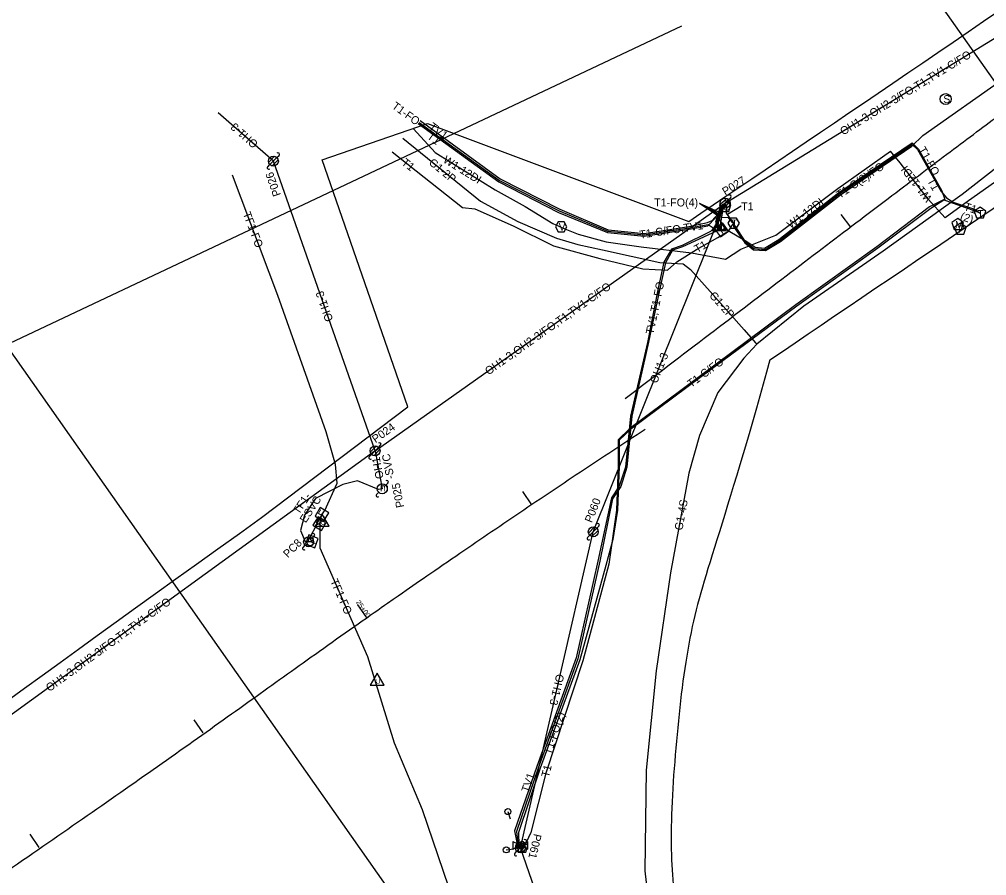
# Model space of a CAD drawing. Extents: x 1991878 to 2008544, y 770238 to 1141211.
# Drawn here: x 2004972.5 to 2005456, y 1139564 to 1139992.3 of the extents above; entities that cross this region are included whole.
import ezdxf

# ---------------------------------------------------------------- set-up
doc = ezdxf.new("R2010")
doc.units = 0
for name, color, linetype in [('RD_EX_SU_Elec', 7, 'Continuous'), ('RD_EX_SU_Gas', 7, 'Continuous'), ('RD_EX_SU_H2O', 7, 'Continuous'), ('RD_EX_SU_Misc', 7, 'Continuous'), ('RD_EX_SU_Ovhd', 7, 'Continuous'), ('RD_EX_SU_Pole', 7, 'Continuous'), ('RD_EX_SU_Sewer', 7, 'Continuous'), ('RD_EX_SU_SwpLmt', 7, 'Continuous'), ('RD_EX_SU_Telecom', 7, 'Continuous'), ('RD_EX_SU_Trfc', 7, 'Continuous'), ('RD_EX_SU_TX_Gas', 7, 'Continuous'), ('RD_EX_SU_TX_H2O', 7, 'Continuous'), ('RD_EX_SU_TX_Ovhd', 7, 'Continuous'), ('RD_EX_SU_TX_Pole', 7, 'Continuous'), ('RD_EX_SU_TX_Telecom', 7, 'Continuous'), ('RD_EX_SU_TX_Trfc', 7, 'Continuous'), ('RD_HC_Cl', 7, 'Continuous')]:
    doc.layers.add(name, color=color, linetype=linetype)

# ---------------------------------------------------------------- blocks, each defined once
blk = doc.blocks.new('GW')
at = {"layer": 'RD_EX_SU_Pole'}
blk.add_line((0, 0), (0, 5), dxfattribs=at)
blk.add_circle((0, 0), 2, dxfattribs=at)

msp = doc.modelspace()

# ---------------------------------------------------------------- linework, layer by layer
at = {"layer": 'RD_EX_SU_Elec'}
msp.add_lwpolyline([(2005153.85, 1139757.47), (2005152.02, 1139757.14), (2005141.45, 1139761.42), (2005134.15, 1139759.67), (2005120.43, 1139752.58), (2005114.98, 1139744.32), (2005113, 1139736.52), (2005115.35, 1139731.05), (2005117.06, 1139730.96)], dxfattribs=at)
at = {"layer": 'RD_EX_SU_Gas'}
for points in [[(2005803.2, 1140176.39), (2005763.13, 1140146.95), (2005723.81, 1140118.19), (2005683.92, 1140086.83), (2005644.62, 1140056.74), (2005604.18, 1140027.33), (2005564.31, 1139998.64), (2005521.91, 1139966.72), (2005504.56, 1139952.57), (2005484.04, 1139936.17), (2005443.65, 1139904.67), (2005433.24, 1139897.21), (2005404.27, 1139876.33), (2005364.62, 1139848.8), (2005341.03, 1139829.73), (2005334.6, 1139822.82), (2005321.62, 1139805.66), (2005312.49, 1139784.03), (2005307.05, 1139765.3), (2005297.89, 1139715.34), (2005290.82, 1139666.35), (2005285.78, 1139616.8), (2005285.17, 1139566.36), (2005290.52, 1139518.04)], [(2005164.18, 1139932.85), (2005202.91, 1139901.24), (2005221.58, 1139891.11), (2005240.96, 1139882.82), (2005251.57, 1139879.59), (2005264.01, 1139876.97), (2005292.58, 1139870.62), (2005304.26, 1139870.04), (2005307.88, 1139867.17), (2005317.77, 1139856.07), (2005334.76, 1139836.96), (2005340.45, 1139830.49), (2005341.03, 1139829.73)]]:
    msp.add_lwpolyline(points, dxfattribs=at)
at = {"layer": 'RD_EX_SU_H2O'}
for points in [[(2005807.57, 1140171.15), (2005766.02, 1140142.13), (2005735.93, 1140120.52), (2005732.28, 1140118.09), (2005726.84, 1140114.53), (2005714.88, 1140105.91), (2005686.65, 1140083.86), (2005647.25, 1140052.78), (2005607.69, 1140020.33), (2005569.36, 1139991.81), (2005526.81, 1139959.7), (2005492.34, 1139933.84), (2005487.01, 1139929.87), (2005446.84, 1139901.54), (2005435.17, 1139892.92), (2005426.67, 1139902.32), (2005412.65, 1139920.51), (2005407.97, 1139926.34)], [(2005169.51, 1139937.42), (2005180.22, 1139925.59), (2005210.25, 1139906.98), (2005225.26, 1139898.61), (2005239.13, 1139890.18), (2005245.16, 1139887.44), (2005251.72, 1139884.74), (2005265.7, 1139881), (2005283.32, 1139878.42), (2005308.46, 1139875.51), (2005325.36, 1139872.3), (2005333.15, 1139877.37), (2005350.62, 1139884.25), (2005381.59, 1139907.64), (2005407.97, 1139926.34)]]:
    msp.add_lwpolyline(points, dxfattribs=at)
for points in [[(2005246.17, 1139888.44), (2005244.72, 1139890.94), (2005241.84, 1139890.94), (2005240.39, 1139888.44), (2005241.84, 1139885.94), (2005244.72, 1139885.94)], [(2005441.53, 1139892.71), (2005438.62, 1139890.6), (2005439.73, 1139887.19), (2005443.32, 1139887.19), (2005444.43, 1139890.6)], [(2005442.82, 1139890.37), (2005439.92, 1139888.27), (2005441.03, 1139884.86), (2005444.61, 1139884.86), (2005445.72, 1139888.27)]]:
    msp.add_lwpolyline(points, close=True, dxfattribs=at)
at = {"layer": 'RD_EX_SU_Misc'}
for points in [[(2005322.31, 1139892.63), (2005318.84, 1139886.63), (2005325.77, 1139886.63)], [(2005123.83, 1139744.73), (2005120.37, 1139738.73), (2005127.3, 1139738.73)], [(2005151.32, 1139665.16), (2005147.86, 1139659.16), (2005154.79, 1139659.16)]]:
    msp.add_lwpolyline(points, close=True, dxfattribs=at)
at = {"layer": 'RD_EX_SU_Ovhd'}
for p, q in [((2005325.23, 1139900.3), (2005507.86, 1140012.14)), ((2005099.43, 1139921.35), (2005071.87, 1139945.5)), ((2005150.23, 1139776.39), (2005099.43, 1139921.35)), ((2005150.23, 1139776.39), (2005325.23, 1139900.3)), ((2005259.34, 1139735.98), (2005325.23, 1139900.3)), ((2005150.23, 1139776.39), (2004885.7, 1139584.32)), ((2005150.23, 1139776.39), (2005153.85, 1139757.47)), ((2005222.89, 1139577.92), (2005259.34, 1139735.98)), ((2005312.61, 1139322.78), (2005222.89, 1139577.92))]:
    msp.add_line(p, q, dxfattribs=at)
at = {"layer": 'RD_EX_SU_Pole'}
for p, q in [((2005097.01, 1139920.7), (2005100.07, 1139923.76)), ((2005097.66, 1139919.58), (2005101.19, 1139923.12)), ((2005098.78, 1139918.93), (2005101.84, 1139922)), ((2005101.19, 1139923.12), (2005102.25, 1139924.18)), ((2005096.6, 1139918.52), (2005097.66, 1139919.58)), ((2005322.81, 1139899.65), (2005325.88, 1139902.71)), ((2005323.46, 1139898.53), (2005327, 1139902.07)), ((2005324.58, 1139897.88), (2005327.64, 1139900.94)), ((2005327, 1139902.07), (2005328.06, 1139903.13)), ((2005322.4, 1139897.47), (2005323.46, 1139898.53)), ((2005147.81, 1139775.74), (2005150.87, 1139778.8)), ((2005148.46, 1139774.62), (2005151.99, 1139778.16)), ((2005149.58, 1139773.98), (2005152.64, 1139777.04)), ((2005151.99, 1139778.16), (2005153.05, 1139779.22)), ((2005147.4, 1139773.56), (2005148.46, 1139774.62)), ((2005155.62, 1139759.24), (2005156.68, 1139760.3)), ((2005151.02, 1139754.65), (2005152.08, 1139755.71)), ((2005256.92, 1139735.33), (2005259.98, 1139738.4)), ((2005257.57, 1139734.21), (2005261.1, 1139737.75)), ((2005258.69, 1139733.57), (2005261.75, 1139736.63)), ((2005261.1, 1139737.75), (2005262.16, 1139738.81)), ((2005256.51, 1139733.15), (2005257.57, 1139734.21)), ((2005220.48, 1139577.27), (2005223.54, 1139580.33)), ((2005221.13, 1139576.15), (2005224.66, 1139579.68)), ((2005222.25, 1139575.5), (2005225.31, 1139578.56)), ((2005224.66, 1139579.68), (2005225.72, 1139580.74)), ((2005220.07, 1139575.09), (2005221.13, 1139576.15))]:
    msp.add_line(p, q, dxfattribs=at)
for centre in [(2005099.43, 1139921.35), (2005325.23, 1139900.3), (2005150.23, 1139776.39), (2005153.85, 1139757.47), (2005259.34, 1139735.98), (2005222.89, 1139577.92)]:
    msp.add_circle(centre, 2.5, dxfattribs=at)
for centre, start, end in [((2005101.72, 1139924.71), 315.0116, 135.0116), ((2005097.13, 1139917.99), 135.0116, 315.0116), ((2005327.53, 1139903.66), 315.0116, 135.0116), ((2005322.93, 1139896.94), 135.0116, 315.0116), ((2005152.52, 1139779.75), 315.0116, 135.0116), ((2005147.93, 1139773.03), 135.0116, 315.0116), ((2005156.15, 1139760.83), 315.0116, 135.0116), ((2005151.55, 1139754.11), 135.0116, 315.0116), ((2005261.63, 1139739.34), 315.0116, 135.0116), ((2005257.04, 1139732.62), 135.0116, 315.0116), ((2005225.19, 1139581.28), 315.0116, 135.0116), ((2005220.6, 1139574.56), 135.0116, 315.0116)]:
    msp.add_arc(centre, 0.75, start, end, dxfattribs=at)
at = {"layer": 'RD_EX_SU_Sewer'}
msp.add_circle((2005435.49, 1139952.36), 2.75, dxfattribs=at)
at = {"layer": 'RD_EX_SU_SwpLmt'}
for p, q in [((2005123.81, 1139921.92), (2005176.42, 1139940.17)), ((2005176.42, 1139940.17), (2005307.04, 1139891.13)), ((2005166.65, 1139798.43), (2005123.81, 1139921.92)), ((2005093.47, 1139743.03), (2005166.65, 1139798.43))]:
    msp.add_line(p, q, dxfattribs=at)
for points in [[(2005347.6, 1139821.95), (2005413.49, 1139866.73), (2005588.16, 1139984.08), (2005817.83, 1140151.69), (2006031.43, 1140278.81), (2006110.28, 1140318.03), (2006387.29, 1140416.7), (2006495.91, 1140463.06), (2006601.39, 1140518.44), (2006718.46, 1140585.62), (2006783.57, 1140627.26), (2006823.57, 1140659.06)], [(2005347.6, 1139821.95), (2005413.49, 1139866.73), (2005588.16, 1139984.08), (2005817.83, 1140151.69), (2006031.43, 1140278.81), (2006110.28, 1140318.03), (2006387.29, 1140416.7), (2006495.91, 1140463.06), (2006601.39, 1140518.44), (2006706.19, 1140578.58), (2006762.55, 1140613.92), (2006787.85, 1140632.08)], [(2005307.04, 1139891.13), (2005371.11, 1139934.66), (2005544.09, 1140050.96), (2005773.7, 1140218.52), (2005993.11, 1140349.1), (2006068.08, 1140386.39), (2006199.13, 1140434.31), (2006247.03, 1140451.84)], [(2005347.6, 1139821.95), (2005338.82, 1139789.17), (2005319.63, 1139726.83), (2005307.21, 1139688.02), (2005300.75, 1139635.07), (2005296.98, 1139579.17), (2005300.89, 1139544.34), (2005306.71, 1139501.41), (2005336.4, 1139410.85), (2005354.58, 1139357.93), (2005354.93, 1139356.91), (2005370.8, 1139309.82)], [(2004667.64, 1139426.86), (2004691.38, 1139445.04), (2004818.69, 1139542.26), (2004974.3, 1139658.1), (2005093.47, 1139743.03)]]:
    msp.add_open_spline(points, degree=3, dxfattribs=at)
at = {"layer": 'RD_EX_SU_Telecom'}
for p, q in [((2005325.27, 1139898.61), (2005325.23, 1139900.3)), ((2005219.19, 1139581.04), (2005221.59, 1139579.84)), ((2005219.19, 1139581.04), (2005219.19, 1139577.29)), ((2005219.19, 1139577.29), (2005221.59, 1139578.5)), ((2005224.28, 1139579.84), (2005226.69, 1139581.04)), ((2005224.28, 1139578.5), (2005226.69, 1139577.29)), ((2005226.69, 1139577.29), (2005226.69, 1139581.04))]:
    msp.add_line(p, q, dxfattribs=at)
for points in [[(2005329.54, 1139890.24), (2005329.5, 1139888.67), (2005335.08, 1139880.48), (2005339.37, 1139876.95), (2005345.48, 1139876.61), (2005352.84, 1139881.19), (2005382.96, 1139904.56), (2005418.59, 1139928.8), (2005424.14, 1139934.13), (2005465.15, 1139963.24), (2005505.66, 1139991.65), (2005514.4, 1139998.22), (2005511.6, 1140003.28), (2005507.15, 1140008.6), (2005506.12, 1140009.88)], [(2005171.75, 1139940.12), (2005212.08, 1139911), (2005241.92, 1139895.72), (2005266.39, 1139885.63), (2005284.76, 1139883.81), (2005307.34, 1139887.23), (2005316.54, 1139888.98), (2005320.48, 1139892.91), (2005326.52, 1139893.28), (2005328.52, 1139890.85), (2005329.54, 1139890.24)], [(2005172.34, 1139940.64), (2005212.43, 1139911.58), (2005242.31, 1139896.48), (2005266.6, 1139886.33), (2005284.77, 1139884.5), (2005307.19, 1139887.91), (2005316.75, 1139889.61), (2005320.71, 1139887.02), (2005323.48, 1139886.9)], [(2005172.72, 1139941.65), (2005212.71, 1139912.43), (2005242.55, 1139897.35), (2005266.74, 1139886.95), (2005284.79, 1139885.19), (2005307.04, 1139888.71), (2005316.48, 1139890.57), (2005318.72, 1139891.61), (2005324.67, 1139898.08), (2005325.27, 1139898.61)], [(2005323.48, 1139886.9), (2005325.65, 1139887.26), (2005336.03, 1139881.17), (2005340.25, 1139878.22), (2005344.85, 1139877.72), (2005352.12, 1139882.19), (2005382.15, 1139905.62), (2005418.71, 1139930.43), (2005421.88, 1139927.35), (2005433.64, 1139906.53), (2005435.1, 1139902.1), (2005428.12, 1139897.63), (2005401.53, 1139877.88), (2005361, 1139848.83), (2005313.26, 1139813.53), (2005278.11, 1139787.32), (2005272.33, 1139781.85), (2005272.33, 1139768.79), (2005271.52, 1139746.7), (2005269.11, 1139732.16), (2005265.54, 1139719.16), (2005252.68, 1139671.84), (2005232.78, 1139617.8), (2005222.03, 1139585.56), (2005222.06, 1139579.11), (2005222.89, 1139577.92)], [(2005329.54, 1139890.24), (2005329.86, 1139889.11), (2005335.43, 1139880.78), (2005339.78, 1139877.62), (2005345.17, 1139877.11), (2005352.59, 1139881.68), (2005382.53, 1139905.07), (2005418.67, 1139929.59), (2005421.43, 1139927.09), (2005433.28, 1139906.21), (2005435.94, 1139902.99), (2005439.28, 1139900.88), (2005449.89, 1139897.26), (2005452.64, 1139895.36)], [(2005158.82, 1139925.96), (2005194.01, 1139898.12), (2005200.13, 1139897.55), (2005219.33, 1139888.94), (2005239.37, 1139879.01), (2005262.65, 1139872.69), (2005284.07, 1139867.44), (2005296.49, 1139866.87), (2005301.04, 1139871.01), (2005310.97, 1139877.21), (2005321.57, 1139883.12), (2005327.15, 1139886.4), (2005328.52, 1139889), (2005329.54, 1139890.24)], [(2005452.64, 1139895.36), (2005449.47, 1139896.61), (2005438.94, 1139900.34), (2005434.37, 1139902.01), (2005427.42, 1139898.46), (2005401.04, 1139878.44), (2005360.59, 1139849.53), (2005312.98, 1139813.98), (2005277.67, 1139787.66), (2005271.77, 1139782), (2005271.7, 1139768.83), (2005270.97, 1139746.75), (2005267.19, 1139719.78), (2005254.18, 1139671.36), (2005235.57, 1139615.19), (2005228.17, 1139585.63), (2005224.84, 1139578.41), (2005223.84, 1139578.16), (2005223.71, 1139577.39), (2005222.89, 1139577.92)], [(2005325.27, 1139898.61), (2005324.71, 1139899.01), (2005319.93, 1139888.26), (2005317.91, 1139886.18), (2005303.76, 1139879.2), (2005298.48, 1139877.27), (2005294.63, 1139870.79), (2005291.63, 1139856.89), (2005286.38, 1139830.63), (2005277.9, 1139793.72), (2005275.51, 1139768.28), (2005272.34, 1139758.76), (2005268.4, 1139752.91), (2005261.58, 1139721.28), (2005250.82, 1139672.9), (2005231.12, 1139618.56), (2005220.01, 1139586.46), (2005221.65, 1139577.98), (2005222.89, 1139577.92)], [(2005325.23, 1139900.3), (2005323, 1139898.99), (2005320.44, 1139890.77), (2005321.37, 1139887.39), (2005323.48, 1139886.9)], [(2005325.23, 1139900.3), (2005323.35, 1139898.74), (2005320.98, 1139890.71), (2005321.94, 1139887.71), (2005323.48, 1139886.9)], [(2005325.23, 1139900.3), (2005323.83, 1139898.59), (2005321.82, 1139890.38), (2005322.56, 1139888.17), (2005323.48, 1139886.9)], [(2005325.23, 1139900.3), (2005324.19, 1139898.49), (2005322.85, 1139890.39), (2005323.22, 1139888.38), (2005323.48, 1139886.9)], [(2005329.54, 1139890.24), (2005329.07, 1139891.15), (2005327.21, 1139893.53), (2005325.88, 1139895.39), (2005326.16, 1139899.01), (2005325.45, 1139899.44), (2005325.23, 1139900.3)], [(2005323.48, 1139886.9), (2005320.99, 1139886.27), (2005303.92, 1139878.54), (2005299.01, 1139876.77), (2005295.36, 1139870.46), (2005292.36, 1139856.76), (2005286.91, 1139830.72), (2005278.61, 1139793.76), (2005276.08, 1139768.26), (2005273.03, 1139758.57), (2005268.9, 1139752.48), (2005262.55, 1139721.27), (2005251.64, 1139672.45), (2005231.98, 1139618.24), (2005220.92, 1139586.11), (2005221.87, 1139578.44), (2005222.89, 1139577.92)], [(2005222.94, 1139579.17), (2005223.62, 1139579.04), (2005223.84, 1139578.16)], [(2005223.84, 1139578.16), (2005223.55, 1139578.61), (2005222.94, 1139579.17)]]:
    msp.add_lwpolyline(points, dxfattribs=at)
for points in [[(2005325.27, 1139901.61), (2005322.42, 1139899.54), (2005323.51, 1139896.18), (2005327.03, 1139896.18), (2005328.12, 1139899.54)], [(2005452.64, 1139898.36), (2005449.79, 1139896.29), (2005450.88, 1139892.94), (2005454.41, 1139892.94), (2005455.5, 1139896.29)], [(2005332.43, 1139890.24), (2005330.99, 1139892.74), (2005328.1, 1139892.74), (2005326.66, 1139890.24), (2005328.1, 1139887.74), (2005330.99, 1139887.74)], [(2005324.08, 1139890.39), (2005320, 1139887.5), (2005322.89, 1139883.42), (2005326.97, 1139886.31)], [(2005223.84, 1139581.16), (2005220.99, 1139579.09), (2005222.08, 1139575.73), (2005225.61, 1139575.73), (2005226.7, 1139579.09)]]:
    msp.add_lwpolyline(points, close=True, dxfattribs=at)
msp.add_circle((2005222.94, 1139579.17), 1.5, dxfattribs=at)
at = {"layer": 'RD_EX_SU_Trfc'}
for p, q in [((2005118.83, 1139732.73), (2005119.89, 1139733.79)), ((2005114.24, 1139728.13), (2005115.3, 1139729.19))]:
    msp.add_line(p, q, dxfattribs=at)
for points in [[(2005117.06, 1139730.96), (2005118.67, 1139731.18), (2005117.63, 1139733), (2005121.11, 1139739.66), (2005122.6, 1139740.05), (2005123.69, 1139744.6), (2005125.1, 1139746.6), (2005131.24, 1139760.29), (2005130.4, 1139769.68), (2005125.75, 1139785.91), (2005101.72, 1139854.1), (2005079.02, 1139914.26)], [(2005122.6, 1139740.05), (2005122.66, 1139727.93), (2005146.49, 1139673.59), (2005159.73, 1139630.34), (2005173.87, 1139597.08), (2005202.6, 1139512.33)]]:
    msp.add_lwpolyline(points, dxfattribs=at)
for points in [[(2005122.89, 1139748.04), (2005120.25, 1139743.79), (2005124.49, 1139741.15), (2005127.13, 1139745.4)], [(2005121.8, 1139743.49), (2005119.16, 1139739.25), (2005123.41, 1139736.61), (2005126.05, 1139740.85)], [(2005117.22, 1139734.4), (2005115.45, 1139729.72), (2005120.12, 1139727.95), (2005121.89, 1139732.63)]]:
    msp.add_lwpolyline(points, close=True, dxfattribs=at)
msp.add_circle((2005117.06, 1139730.96), 2.5, dxfattribs=at)
for centre, start, end in [((2005119.36, 1139734.32), 314.9993, 134.9993), ((2005114.77, 1139727.6), 134.9993, 314.9993)]:
    msp.add_arc(centre, 0.75, start, end, dxfattribs=at)
at = {"layer": 'RD_EX_SU_TX_Telecom'}
for p, q in [((2005323.39, 1139893.63), (2005312.48, 1139900.22)), ((2005322.56, 1139893.38), (2005312.48, 1139900.22)), ((2005312.48, 1139900.22), (2005322.23, 1139894.96)), ((2005322.02, 1139895.84), (2005312.48, 1139900.22)), ((2005333.28, 1139898.75), (2005326.42, 1139894.63))]:
    msp.add_line(p, q, dxfattribs=at)
at = {"layer": 'RD_HC_Cl'}
for p, q in [((2005272.89, 1140227.22), (2005691.71, 1139631.08)), ((2005303.45, 1139988.79), (2004595.02, 1139654.18)), ((2004880.13, 1139951.28), (2005298.96, 1139355.14)), ((2005383.05, 1139894.65), (2005387.87, 1139888.26)), ((2005223.99, 1139756.09), (2005228.47, 1139749.46)), ((2005141.5, 1139699.36), (2005146.07, 1139692.8)), ((2005059.59, 1139641.94), (2005064.19, 1139635.4)), ((2004977.69, 1139584.65), (2004982.25, 1139578.08))]:
    msp.add_line(p, q, dxfattribs=at)
for points in [[(2005275.25, 1139802.58), (2005417.33, 1139911.24), (2005548.93, 1140008.55), (2005664.1, 1140090.03), (2005747, 1140153.49), (2005819.82, 1140205.85), (2005880.88, 1140246.35), (2005986.62, 1140308.11), (2006024.68, 1140326.82), (2006100.51, 1140359.48), (2006273.91, 1140424.96), (2006364.15, 1140455.15), (2006461.52, 1140489.97), (2006524.81, 1140519.99), (2006584.45, 1140553.16), (2006699.96, 1140622.09), (2006754.11, 1140664.4), (2006830.67, 1140723.8), (2007317.85, 1141134.95)], [(2002937.27, 1138556.06), (2003081.12, 1138596.24), (2003224.54, 1138636.27), (2003324.8, 1138664.72), (2003440.8, 1138697.76), (2003610.3, 1138743.13), (2003753.45, 1138782.34), (2003851.96, 1138815.09), (2003945.32, 1138855.48), (2004023.07, 1138899.74), (2004117.46, 1138962.96), (2004239.69, 1139051.13), (2004401.3, 1139168.16), (2004522.74, 1139256.47), (2004724.1, 1139402.13), (2005003.72, 1139590.96), (2005189.76, 1139724.82), (2005285.27, 1139787.25)]]:
    msp.add_open_spline(points, degree=2, dxfattribs=at)

# ---------------------------------------------------------------- block references
at = {"layer": 'RD_EX_SU_Pole', "yscale": 0.75}
for p, xscale, rotation in [((2005216.64, 1139596.01), 0.7500000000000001, -160.86037535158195), ((2005215.87, 1139576.85), 0.75, -81.39425926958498)]:
    msp.add_blockref('GW', p, dxfattribs=dict(at, xscale=xscale, rotation=rotation))

# ---------------------------------------------------------------- texts
at = {"layer": 'RD_EX_SU_H2O'}
for s, p in [('M', (2005440.16, 1139887.66)), ('V', (2005242.07, 1139886.56))]:
    msp.add_text(s, height=3.75, dxfattribs=at).set_placement(p)
msp.add_text('P', height=3.75, rotation=360, dxfattribs=at).set_placement((2005441.67, 1139885.45))
at = {"layer": 'RD_EX_SU_Misc'}
for p in [(2005321.55, 1139887.43), (2005123.08, 1139739.53), (2005150.57, 1139659.96)]:
    msp.add_text('U', height=2.4, dxfattribs=at).set_placement(p)
at = {"layer": 'RD_EX_SU_Pole'}
msp.add_text('m', height=4, rotation=0.0116, dxfattribs=at).set_placement((2005152.66, 1139756.15))
at = {"layer": 'RD_EX_SU_Sewer'}
msp.add_text('S', height=3.93, dxfattribs=at).set_placement((2005434.29, 1139950.39))
at = {"layer": 'RD_EX_SU_Telecom'}
for s, height, p in [('C', 4, (2005324.04, 1139896.61)), ('T', 3.75, (2005451.42, 1139893.14)), ('T', 3.75, (2005328.33, 1139888.37)), ('T', 3.75, (2005222.61, 1139575.93))]:
    msp.add_text(s, height=height, dxfattribs=at).set_placement(p)
msp.add_text('F', height=4, rotation=35.2997, dxfattribs=at).set_placement((2005323.71, 1139884.61))
at = {"layer": 'RD_EX_SU_Trfc'}
for s, rotation, p in [('F', 58.1211, (2005124.79, 1139742.58)), ('F', 58.1211, (2005123.7, 1139738.03)), ('O', 359.9993, (2005115.77, 1139728.96)), ('F', 69.3005, (2005120.14, 1139729.41))]:
    msp.add_text(s, height=4, rotation=rotation, dxfattribs=at).set_placement(p)
at = {"layer": 'RD_EX_SU_TX_Gas'}
for s, rotation, p in [('G1-2P', 320.7695, (2005176.77, 1139920)), ('G1-2P', 311.6381, (2005317.03, 1139853.91)), ('G1-4S', 79.6103, (2005303.82, 1139736.43))]:
    msp.add_text(s, height=4, rotation=rotation, dxfattribs=at).set_placement(p)
at = {"layer": 'RD_EX_SU_TX_H2O'}
for rotation, p in [(328.2106, (2005183.9, 1139920.96)), (127.5993, (2005428.86, 1139902.76)), (37.0621, (2005358.07, 1139887.34))]:
    msp.add_text('W1-12DI', height=4, rotation=rotation, dxfattribs=at).set_placement(p)
at = {"layer": 'RD_EX_SU_TX_Ovhd'}
for s, rotation, p in [('OH1-3,OH2-3/FO,T1,TV1-C/FO', 31.483, (2005384.25, 1139934.1)), ('OH1-3', 138.7664, (2005092.11, 1139930.42)), ('OH1-3,OH2-3/FO,T1,TV1-C/FO', 35.2997, (2005206.98, 1139814.12)), ('OH1-3', 109.3131, (2005129.4, 1139841.87)), ('OH1-3', 68.1488, (2005291.12, 1139809.86)), ('-SVC', 100.8397, (2005159.94, 1139762.72)), ('OH1', 100.8397, (2005154.61, 1139762.84)), ('OH1-3,OH2-3/FO,T1,TV1-C/FO', 35.9824, (2004987.5, 1139655.77)), ('OH1-3', 257.0169, (2005240.94, 1139665.09))]:
    msp.add_text(s, height=4, rotation=rotation, dxfattribs=at).set_placement(p)
at = {"layer": 'RD_EX_SU_TX_Pole'}
for s, rotation, p in [('P026', 109.3131, (2005103.25, 1139904.5)), ('P027', 31.483, (2005325.3, 1139904.05)), ('P024', 35.2997, (2005150.51, 1139780.19)), ('P025', 100.8397, (2005164.81, 1139748.37)), ('P060', 68.1488, (2005258.59, 1139740.19)), ('PC8', 44.9993, (2005106.7, 1139722.65)), ('P061', 257.0169, (2005229.66, 1139585.18))]:
    msp.add_text(s, height=4, rotation=rotation, dxfattribs=at).set_placement(p)
at = {"layer": 'RD_EX_SU_TX_Telecom'}
for s, rotation, p in [('T1-FO', 324.0672, (2005158.31, 1139948.07)), ('TV1', 323.8486, (2005176.83, 1139937.72)), ('T1', 324.1691, (2005175.91, 1139932.9)), ('T1-FO', 299.4444, (2005421.64, 1139927.15)), ('T1', 321.6536, (2005163.17, 1139919.97)), ('T1-C(2)/FO', 34.2276, (2005382.55, 1139902.42)), ('T1', 299.5678, (2005426.06, 1139911.5)), ('T1-FO(4)', 359.9993, (2005289.75, 1139898.67)), ('T1', 359.9993, (2005333.24, 1139896.73)), ('T1', 340.532, (2005444.26, 1139897.02)), ('(2)', 340.532, (2005442.36, 1139892.17)), ('T1-C/FO,TV1', 8.6555, (2005282.77, 1139882.53)), ('T1', 29.1808, (2005311.2, 1139875.3)), ('TV1,T1-FO', 78.1701, (2005289.37, 1139834.43)), ('T1-C/FO', 36.4829, (2005308.23, 1139807.88)), ('T1-FO(2)', 71.5554, (2005238.22, 1139624.2)), ('T1', 75.9607, (2005237.13, 1139612.84)), ('TV1', 70.9067, (2005227.01, 1139605.23))]:
    msp.add_text(s, height=4, rotation=rotation, dxfattribs=at).set_placement(p)
at = {"layer": 'RD_EX_SU_TX_Trfc'}
for s, rotation, p in [('TF1-FO', 290.6677, (2005084.12, 1139895.11)), ('TF1-', 56.5678, (2005112.18, 1139744.32)), ('ESVC', 56.5678, (2005115.61, 1139740.06)), ('TF1-FO', 293.6762, (2005127.77, 1139711.33))]:
    msp.add_text(s, height=4, rotation=rotation, dxfattribs=at).set_placement(p)
at = {"layer": 'RD_HC_Cl'}
msp.add_text('25+00', height=2.5, rotation=304.872, dxfattribs=at).set_placement((2005140.61, 1139700.65))

doc.saveas('drawing.dxf')
